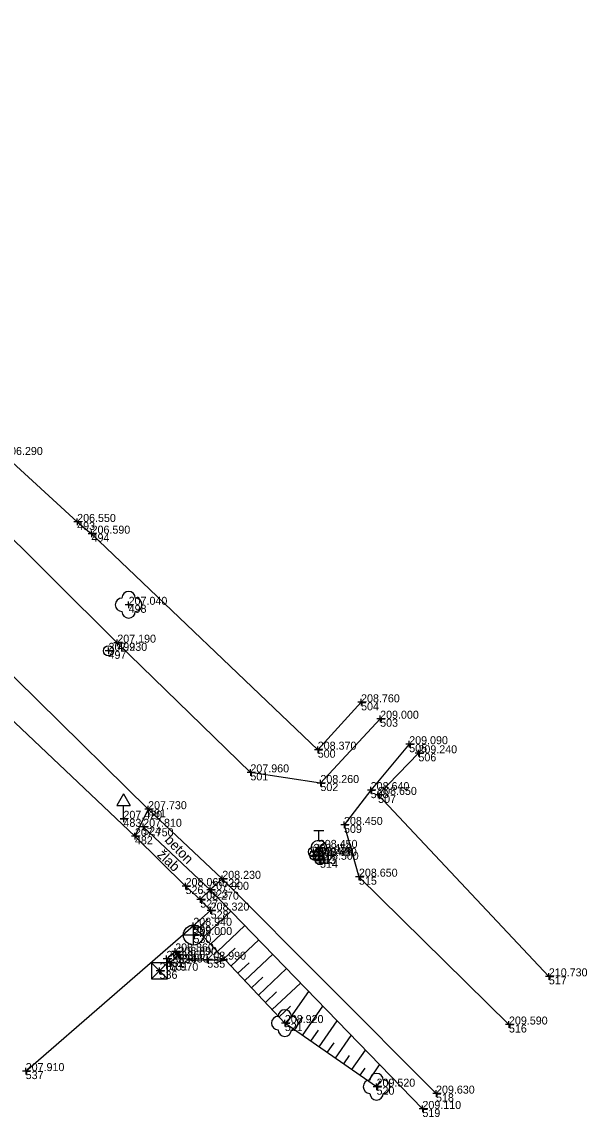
# Model space of a CAD drawing. Extents: x -744883 to -744469, y -966832 to -966374.
# Drawn here: x -744511.3 to -744468.9, y -966832.1 to -966750.1 of the extents above; entities that cross this region are included whole.
import ezdxf

# ---------------------------------------------------------------- set-up
doc = ezdxf.new("R2010")
doc.units = 0
for name, color, linetype in [('Body - výška', 7, 'Continuous'), ('Body - značka', 7, 'Continuous'), ('Body - číslo', 7, 'Continuous'), ('Body polohopisu', 7, 'Continuous'), ('Doplňkové značky', 7, 'Continuous'), ('Nezařazené objekty', 7, 'Continuous'), ('Ploty_opěrné zdi', 7, 'Continuous'), ('Popisy objektů_povrchů', 7, 'Continuous'), ('Rozhraní ploch', 7, 'Continuous'), ('Stromy_porost', 7, 'Continuous'), ('Vrstva 36', 7, 'Continuous'), ('Vstup na pozemek', 7, 'Continuous'), ('Výškopis', 7, 'Continuous'), ('Výšky bodů', 7, 'Continuous'), ('Značky IS', 7, 'Continuous'), ('Čísla bodů', 7, 'Continuous')]:
    doc.layers.add(name, color=color, linetype=linetype)

msp = doc.modelspace()

# ---------------------------------------------------------------- linework, layer by layer
at = {"layer": 'Body - značka'}
for q in [(-744497.66, -966820.35), (-744497.41, -966820.1), (-744497.16, -966820.35), (-744497.41, -966820.6)]:
    msp.add_line((-744497.41, -966820.35), q, dxfattribs=at)
at = {"layer": 'Body polohopisu'}
for p, q in [((-744507.17, -966787.54), (-744507.42, -966787.54)), ((-744507.17, -966787.54), (-744507.17, -966787.29)), ((-744507.17, -966787.54), (-744506.92, -966787.54)), ((-744507.17, -966787.54), (-744507.17, -966787.79)), ((-744506.09, -966788.42), (-744506.34, -966788.42)), ((-744506.09, -966788.42), (-744506.09, -966788.17)), ((-744506.09, -966788.42), (-744505.84, -966788.42)), ((-744506.09, -966788.42), (-744506.09, -966788.67)), ((-744503.31, -966793.75), (-744503.56, -966793.75)), ((-744503.31, -966793.75), (-744503.31, -966793.5)), ((-744503.31, -966793.75), (-744503.06, -966793.75)), ((-744503.31, -966793.75), (-744503.31, -966794)), ((-744504.16, -966796.59), (-744504.41, -966796.59)), ((-744504.16, -966796.59), (-744504.16, -966796.34)), ((-744504.16, -966796.59), (-744503.91, -966796.59)), ((-744504.16, -966796.59), (-744504.16, -966796.84)), ((-744504.82, -966797.2), (-744505.07, -966797.2)), ((-744504.82, -966797.2), (-744504.82, -966796.95)), ((-744504.82, -966797.2), (-744504.57, -966797.2)), ((-744504.82, -966797.2), (-744504.82, -966797.45)), ((-744485.88, -966801.06), (-744485.88, -966800.81)), ((-744485.88, -966801.06), (-744486.13, -966801.06)), ((-744485.88, -966801.06), (-744485.63, -966801.06)), ((-744485.88, -966801.06), (-744485.88, -966801.31)), ((-744484.45, -966802.29), (-744484.7, -966802.29)), ((-744484.45, -966802.29), (-744484.45, -966802.04)), ((-744484.45, -966802.29), (-744484.2, -966802.29)), ((-744484.45, -966802.29), (-744484.45, -966802.54)), ((-744482.27, -966804.2), (-744482.27, -966803.95)), ((-744489.13, -966804.61), (-744489.38, -966804.61)), ((-744489.13, -966804.61), (-744489.13, -966804.36)), ((-744489.13, -966804.61), (-744488.88, -966804.61)), ((-744489.13, -966804.61), (-744489.13, -966804.86)), ((-744482.27, -966804.2), (-744482.52, -966804.2)), ((-744482.27, -966804.2), (-744482.02, -966804.2)), ((-744482.27, -966804.2), (-744482.27, -966804.45)), ((-744481.58, -966804.88), (-744481.83, -966804.88)), ((-744481.58, -966804.88), (-744481.58, -966804.63)), ((-744481.58, -966804.88), (-744481.33, -966804.88)), ((-744481.58, -966804.88), (-744481.58, -966805.13)), ((-744494.18, -966806.31), (-744494.43, -966806.31)), ((-744494.18, -966806.31), (-744494.18, -966806.06)), ((-744494.18, -966806.31), (-744493.93, -966806.31)), ((-744494.18, -966806.31), (-744494.18, -966806.56)), ((-744488.93, -966807.11), (-744489.18, -966807.11)), ((-744488.93, -966807.11), (-744488.93, -966806.86)), ((-744488.93, -966807.11), (-744488.68, -966807.11)), ((-744488.93, -966807.11), (-744488.93, -966807.36)), ((-744485.16, -966807.64), (-744485.16, -966807.39)), ((-744485.16, -966807.64), (-744485.41, -966807.64)), ((-744485.16, -966807.64), (-744484.91, -966807.64)), ((-744485.16, -966807.64), (-744485.16, -966807.89)), ((-744484.6, -966808), (-744484.85, -966808)), ((-744484.6, -966808), (-744484.6, -966807.75)), ((-744484.6, -966808), (-744484.35, -966808)), ((-744484.6, -966808), (-744484.6, -966808.25)), ((-744501.85, -966809.07), (-744501.85, -966808.82)), ((-744503.7, -966809.79), (-744503.95, -966809.79)), ((-744503.7, -966809.79), (-744503.7, -966809.54)), ((-744503.7, -966809.79), (-744503.45, -966809.79)), ((-744503.7, -966809.79), (-744503.7, -966810.04)), ((-744501.85, -966809.07), (-744502.1, -966809.07)), ((-744501.85, -966809.07), (-744501.6, -966809.07)), ((-744501.85, -966809.07), (-744501.85, -966809.32)), ((-744502.22, -966810.39), (-744502.47, -966810.39)), ((-744502.22, -966810.39), (-744502.22, -966810.14)), ((-744502.22, -966810.39), (-744501.97, -966810.39)), ((-744502.22, -966810.39), (-744502.22, -966810.64)), ((-744487.16, -966810.25), (-744487.41, -966810.25)), ((-744487.16, -966810.25), (-744487.16, -966810)), ((-744487.16, -966810.25), (-744486.91, -966810.25)), ((-744487.16, -966810.25), (-744487.16, -966810.5)), ((-744502.84, -966811.1), (-744503.09, -966811.1)), ((-744502.84, -966811.1), (-744502.84, -966810.85)), ((-744502.84, -966811.1), (-744502.59, -966811.1)), ((-744502.84, -966811.1), (-744502.84, -966811.35)), ((-744489.45, -966812.27), (-744489.7, -966812.27)), ((-744489.45, -966812.27), (-744489.45, -966812.02)), ((-744489.45, -966812.27), (-744489.2, -966812.27)), ((-744489.45, -966812.27), (-744489.45, -966812.52)), ((-744489.35, -966812.53), (-744489.35, -966812.28)), ((-744489.05, -966811.97), (-744489.3, -966811.97)), ((-744489.05, -966811.97), (-744489.05, -966811.72)), ((-744489.05, -966811.97), (-744488.8, -966811.97)), ((-744489.05, -966811.97), (-744489.05, -966812.22)), ((-744489.35, -966812.53), (-744489.6, -966812.53)), ((-744489.35, -966812.53), (-744489.1, -966812.53)), ((-744489.35, -966812.53), (-744489.35, -966812.78)), ((-744489.1, -966812.59), (-744489.35, -966812.59)), ((-744488.96, -966812.86), (-744489.21, -966812.86)), ((-744489.1, -966812.59), (-744489.1, -966812.34)), ((-744489.1, -966812.59), (-744488.85, -966812.59)), ((-744489.1, -966812.59), (-744489.1, -966812.84)), ((-744488.96, -966812.86), (-744488.96, -966812.61)), ((-744488.96, -966812.86), (-744488.71, -966812.86)), ((-744488.96, -966812.86), (-744488.96, -966813.11)), ((-744486.04, -966814.13), (-744486.04, -966813.88)), ((-744499.04, -966814.83), (-744499.04, -966814.58)), ((-744496.29, -966814.29), (-744496.54, -966814.29)), ((-744496.29, -966814.29), (-744496.29, -966814.04)), ((-744496.29, -966814.29), (-744496.04, -966814.29)), ((-744496.29, -966814.29), (-744496.29, -966814.54)), ((-744486.04, -966814.13), (-744486.29, -966814.13)), ((-744486.04, -966814.13), (-744485.79, -966814.13)), ((-744486.04, -966814.13), (-744486.04, -966814.38)), ((-744499.04, -966814.83), (-744499.29, -966814.83)), ((-744499.04, -966814.83), (-744498.79, -966814.83)), ((-744499.04, -966814.83), (-744499.04, -966815.08)), ((-744497.94, -966815.85), (-744497.94, -966815.6)), ((-744497.19, -966815.11), (-744497.44, -966815.11)), ((-744497.19, -966815.11), (-744497.19, -966814.86)), ((-744497.19, -966815.11), (-744496.94, -966815.11)), ((-744497.19, -966815.11), (-744497.19, -966815.36)), ((-744497.94, -966815.85), (-744498.19, -966815.85)), ((-744497.94, -966815.85), (-744497.69, -966815.85)), ((-744497.94, -966815.85), (-744497.94, -966816.1)), ((-744497.16, -966816.67), (-744497.16, -966816.42)), ((-744497.16, -966816.67), (-744497.41, -966816.67)), ((-744497.16, -966816.67), (-744496.91, -966816.67)), ((-744497.16, -966816.67), (-744497.16, -966816.92)), ((-744498.46, -966817.81), (-744498.71, -966817.81)), ((-744498.46, -966817.81), (-744498.46, -966817.56)), ((-744498.46, -966817.81), (-744498.21, -966817.81)), ((-744498.46, -966817.81), (-744498.46, -966818.06)), ((-744498.45, -966818.5), (-744498.7, -966818.5)), ((-744498.45, -966818.5), (-744498.45, -966818.25)), ((-744498.45, -966818.5), (-744498.2, -966818.5)), ((-744498.45, -966818.5), (-744498.45, -966818.75)), ((-744499.82, -966819.73), (-744499.82, -966819.48)), ((-744500.47, -966820.29), (-744500.72, -966820.29)), ((-744500.47, -966820.29), (-744500.47, -966820.04)), ((-744500.47, -966820.29), (-744500.22, -966820.29)), ((-744500.47, -966820.29), (-744500.47, -966820.54)), ((-744500.21, -966820.56), (-744500.21, -966820.31)), ((-744499.82, -966819.73), (-744500.07, -966819.73)), ((-744499.58, -966819.99), (-744499.83, -966819.99)), ((-744499.82, -966819.73), (-744499.57, -966819.73)), ((-744499.82, -966819.73), (-744499.82, -966819.98)), ((-744499.58, -966819.99), (-744499.58, -966819.74)), ((-744499.58, -966819.99), (-744499.33, -966819.99)), ((-744499.58, -966819.99), (-744499.58, -966820.24)), ((-744500.99, -966821.18), (-744501.24, -966821.18)), ((-744500.99, -966821.18), (-744500.99, -966820.93)), ((-744500.99, -966821.18), (-744500.74, -966821.18)), ((-744500.99, -966821.18), (-744500.99, -966821.43)), ((-744500.21, -966820.56), (-744500.46, -966820.56)), ((-744500.21, -966820.56), (-744499.96, -966820.56)), ((-744500.21, -966820.56), (-744500.21, -966820.81)), ((-744471.8, -966821.6), (-744471.8, -966821.35)), ((-744471.8, -966821.6), (-744472.05, -966821.6)), ((-744471.8, -966821.6), (-744471.55, -966821.6)), ((-744471.8, -966821.6), (-744471.8, -966821.85)), ((-744491.6, -966825.1), (-744491.85, -966825.1)), ((-744491.6, -966825.1), (-744491.6, -966824.85)), ((-744491.6, -966825.1), (-744491.35, -966825.1)), ((-744491.6, -966825.1), (-744491.6, -966825.35)), ((-744474.79, -966825.21), (-744475.04, -966825.21)), ((-744474.79, -966825.21), (-744474.79, -966824.96)), ((-744474.79, -966825.21), (-744474.54, -966825.21)), ((-744474.79, -966825.21), (-744474.79, -966825.46)), ((-744511.03, -966828.7), (-744511.28, -966828.7)), ((-744511.03, -966828.7), (-744511.03, -966828.45)), ((-744511.03, -966828.7), (-744510.78, -966828.7)), ((-744511.03, -966828.7), (-744511.03, -966828.95)), ((-744484.72, -966829.87), (-744484.97, -966829.87)), ((-744484.72, -966829.87), (-744484.72, -966829.62)), ((-744484.72, -966829.87), (-744484.47, -966829.87)), ((-744484.72, -966829.87), (-744484.72, -966830.12)), ((-744480.26, -966830.39), (-744480.26, -966830.14)), ((-744480.26, -966830.39), (-744480.51, -966830.39)), ((-744480.26, -966830.39), (-744480.01, -966830.39)), ((-744480.26, -966830.39), (-744480.26, -966830.64)), ((-744481.28, -966831.54), (-744481.53, -966831.54)), ((-744481.28, -966831.54), (-744481.28, -966831.29)), ((-744481.28, -966831.54), (-744481.03, -966831.54)), ((-744481.28, -966831.54), (-744481.28, -966831.79))]:
    msp.add_line(p, q, dxfattribs=at)
at = {"layer": 'Doplňkové značky'}
for p, q in [((-744503.7, -966807.924), (-744504.2, -966808.79)), ((-744503.7, -966807.924), (-744503.2, -966808.79)), ((-744504.2, -966808.79), (-744503.2, -966808.79)), ((-744503.7, -966809.79), (-744503.7, -966808.79)), ((-744503.95, -966809.79), (-744503.45, -966809.79))]:
    msp.add_line(p, q, dxfattribs=at)
at = {"layer": 'Nezařazené objekty'}
msp.add_lwpolyline([(-744497.19, -966815.11), (-744502.22, -966810.39)], dxfattribs=at)
at = {"layer": 'Ploty_opěrné zdi'}
for points in [[(-744512.65, -966782.52), (-744507.17, -966787.54)], [(-744506.09, -966788.42), (-744489.13, -966804.61), (-744485.88, -966801.06)], [(-744502.84, -966811.1), (-744520.37, -966794.52)], [(-744481.58, -966804.88), (-744484.6, -966808), (-744471.8, -966821.6)], [(-744511.03, -966828.7), (-744498.46, -966817.81), (-744497.16, -966816.67), (-744497.94, -966815.85), (-744499.04, -966814.83)]]:
    msp.add_lwpolyline(points, dxfattribs=at)
at = {"layer": 'Rozhraní ploch'}
for points in [[(-744484.45, -966802.29), (-744488.93, -966807.11), (-744494.18, -966806.31), (-744504.16, -966796.59), (-744523.84, -966777.07), (-744535.89, -966765.33), (-744540.85, -966760.58), (-744553.38, -966748.22), (-744567.31, -966735.07), (-744575.15, -966727.6), (-744592.64, -966710.64), (-744593.17, -966705.66)], [(-744534.31, -966781.3), (-744531.64, -966779.92), (-744518.41, -966792.79), (-744501.85, -966809.07), (-744502.84, -966811.1)], [(-744482.27, -966804.2), (-744485.16, -966807.64), (-744487.16, -966810.25), (-744486.04, -966814.13), (-744474.79, -966825.21)], [(-744501.85, -966809.07), (-744496.29, -966814.29)], [(-744480.26, -966830.39), (-744496.29, -966814.29), (-744497.19, -966815.11), (-744497.94, -966815.85)]]:
    msp.add_lwpolyline(points, dxfattribs=at)
at = {"layer": 'Stromy_porost'}
for centre in [(-744503.31, -966793.75), (-744491.6, -966825.1), (-744484.72, -966829.87)]:
    msp.add_circle(centre, 0.0005, dxfattribs=at)
for centre, start, end in [((-744503.81, -966793.75), 89.99999, 269.99999), ((-744503.31, -966793.25), 0, 179.99999), ((-744502.81, -966793.75), 270, 89.99999), ((-744503.31, -966794.25), 179.99999, 359.99999), ((-744492.1, -966825.1), 89.99999, 269.99999), ((-744491.6, -966824.6), 0, 179.99999), ((-744491.1, -966825.1), 270, 89.99999), ((-744491.6, -966825.6), 179.99999, 359.99999), ((-744485.22, -966829.87), 89.99999, 269.99999), ((-744484.72, -966829.37), 0, 179.99999), ((-744484.22, -966829.87), 270, 89.99999), ((-744484.72, -966830.37), 179.99999, 359.99999)]:
    msp.add_arc(centre, 0.5, start, end, dxfattribs=at)
at = {"layer": 'Vrstva 36'}
msp.add_line((-744498.91, -966820.35), (-744495.91, -966820.35), dxfattribs=at)
msp.add_lwpolyline([(-744496.91, -966820.1), (-744495.91, -966820.35), (-744496.91, -966820.6)], dxfattribs=at)
at = {"layer": 'Vstup na pozemek'}
for points in [[(-744507.17, -966787.54), (-744506.09, -966788.42)], [(-744499.04, -966814.83), (-744502.84, -966811.1)]]:
    msp.add_lwpolyline(points, dxfattribs=at)
at = {"layer": 'Výškopis'}
for points in [[(-744481.28, -966831.54), (-744497.19, -966815.11)], [(-744497.684, -966818.634), (-744495.64, -966816.711)], [(-744484.72, -966829.87), (-744491.6, -966825.1), (-744498.46, -966817.81)], [(-744498.198, -966818.088), (-744497.384, -966817.322)], [(-744496.656, -966819.727), (-744494.596, -966817.788)], [(-744497.17, -966819.181), (-744496.349, -966818.408)], [(-744495.628, -966820.819), (-744493.553, -966818.866)], [(-744496.142, -966820.273), (-744495.315, -966819.495)], [(-744494.6, -966821.912), (-744492.509, -966819.944)], [(-744495.114, -966821.365), (-744494.281, -966820.581)], [(-744493.572, -966823.004), (-744491.466, -966821.021)], [(-744494.086, -966822.458), (-744493.247, -966821.668)], [(-744492.544, -966824.096), (-744490.422, -966822.099)], [(-744493.058, -966823.55), (-744492.213, -966822.754)], [(-744491.5, -966825.169), (-744489.81, -966822.732)], [(-744492.03, -966824.643), (-744491.178, -966823.841)], [(-744490.267, -966826.024), (-744488.746, -966823.83)], [(-744490.884, -966825.597), (-744490.241, -966824.67)], [(-744489.034, -966826.879), (-744487.682, -966824.928)], [(-744489.651, -966826.451), (-744489.076, -966825.623)], [(-744487.802, -966827.733), (-744486.619, -966826.027)], [(-744488.418, -966827.306), (-744487.911, -966826.575)], [(-744487.185, -966828.161), (-744486.746, -966827.527)], [(-744486.569, -966828.588), (-744485.555, -966827.125)], [(-744485.953, -966829.015), (-744485.581, -966828.479)], [(-744485.336, -966829.443), (-744484.491, -966828.224)], [(-744484.72, -966829.87), (-744484.416, -966829.431)]]:
    msp.add_lwpolyline(points, dxfattribs=at)
at = {"layer": 'Značky IS'}
for p, q in [((-744489.425, -966810.657), (-744488.675, -966810.657)), ((-744489.05, -966811.407), (-744489.05, -966810.657)), ((-744489.491, -966812.317), (-744488.606, -966811.622)), ((-744498.451, -966819.248), (-744498.45, -966817.753)), ((-744497.698, -966818.506), (-744499.198, -966818.501)), ((-744501.59, -966820.58), (-744500.39, -966821.78)), ((-744500.39, -966820.58), (-744501.59, -966821.78))]:
    msp.add_line(p, q, dxfattribs=at)
msp.add_lwpolyline([(-744499.58, -966819.99), (-744500.21, -966820.56), (-744500.47, -966820.29), (-744499.82, -966819.73), (-744499.58, -966819.99)], dxfattribs=at)
msp.add_lwpolyline([(-744501.59, -966821.78), (-744500.39, -966821.78), (-744500.39, -966820.58), (-744501.59, -966820.58)], close=True, dxfattribs=at)
for centre, radius in [((-744504.82, -966797.2), 0.375), ((-744489.05, -966811.97), 0.562), ((-744489.45, -966812.27), 0.375), ((-744489.35, -966812.53), 0.375), ((-744489.1, -966812.59), 0.375), ((-744488.96, -966812.86), 0.375), ((-744498.45, -966818.5), 0.75)]:
    msp.add_circle(centre, radius, dxfattribs=at)

# ---------------------------------------------------------------- texts
at = {"layer": 'Body - výška'}
msp.add_text('208.990', height=0.6, dxfattribs=at).set_placement((-744497.41, -966820.35))
at = {"layer": 'Body - číslo'}
msp.add_text('535', height=0.6, dxfattribs=at).set_placement((-744497.41, -966820.95))
at = {"layer": 'Popisy objektů_povrchů'}
for s, rotation, p in [('beton', 314.01601, (-744500.66, -966811.431)), ('žlab', 316.8211, (-744501.231, -966812.552))]:
    msp.add_text(s, height=0.75, rotation=rotation, dxfattribs=at).set_placement(p)
at = {"layer": 'Výšky bodů'}
for s, p in [('206.290', (-744512.65, -966782.52)), ('206.550', (-744507.17, -966787.54)), ('206.590', (-744506.09, -966788.42)), ('207.040', (-744503.31, -966793.75)), ('207.230', (-744504.82, -966797.2)), ('207.190', (-744504.16, -966796.59)), ('208.760', (-744485.88, -966801.06)), ('209.000', (-744484.45, -966802.29)), ('208.370', (-744489.13, -966804.61)), ('209.090', (-744482.27, -966804.2)), ('209.240', (-744481.58, -966804.88)), ('207.960', (-744494.18, -966806.31)), ('208.260', (-744488.93, -966807.11)), ('208.640', (-744485.16, -966807.64)), ('208.650', (-744484.6, -966808)), ('207.730', (-744501.85, -966809.07)), ('207.420', (-744503.7, -966809.79)), ('207.810', (-744502.22, -966810.39)), ('208.450', (-744487.16, -966810.25)), ('207.750', (-744502.84, -966811.1)), ('208.450', (-744489.05, -966811.97)), ('208.450', (-744489.45, -966812.27)), ('208.470', (-744489.35, -966812.53)), ('208.480', (-744489.1, -966812.59)), ('208.500', (-744488.96, -966812.86)), ('208.230', (-744496.29, -966814.29)), ('208.650', (-744486.04, -966814.13)), ('208.060', (-744499.04, -966814.83)), ('207.900', (-744497.19, -966815.11)), ('208.270', (-744497.94, -966815.85)), ('208.320', (-744497.16, -966816.67)), ('208.940', (-744498.46, -966817.81)), ('209.000', (-744498.45, -966818.5)), ('208.860', (-744500.47, -966820.29)), ('208.860', (-744499.82, -966819.73)), ('208.890', (-744499.58, -966819.99)), ('208.880', (-744500.21, -966820.56)), ('208.970', (-744500.99, -966821.18)), ('210.730', (-744471.8, -966821.6)), ('208.920', (-744491.6, -966825.1)), ('209.590', (-744474.79, -966825.21)), ('207.910', (-744511.03, -966828.7)), ('209.520', (-744484.72, -966829.87)), ('209.630', (-744480.26, -966830.39)), ('209.110', (-744481.28, -966831.54))]:
    msp.add_text(s, height=0.6, dxfattribs=at).set_placement(p)
at = {"layer": 'Čísla bodů'}
for s, p in [('493', (-744507.17, -966788.14)), ('494', (-744506.09, -966789.02)), ('498', (-744503.31, -966794.35)), ('499', (-744504.16, -966797.19)), ('497', (-744504.82, -966797.8)), ('504', (-744485.88, -966801.66)), ('503', (-744484.45, -966802.89)), ('500', (-744489.13, -966805.21)), ('505', (-744482.27, -966804.8)), ('506', (-744481.58, -966805.48)), ('501', (-744494.18, -966806.91)), ('502', (-744488.93, -966807.71)), ('508', (-744485.16, -966808.24)), ('507', (-744484.6, -966808.6)), ('483', (-744503.7, -966810.39)), ('481', (-744501.85, -966809.67)), ('524', (-744502.22, -966810.99)), ('509', (-744487.16, -966810.85)), ('482', (-744502.84, -966811.7)), ('511', (-744489.45, -966812.87)), ('510', (-744489.05, -966812.57)), ('512', (-744489.35, -966813.13)), ('513', (-744489.1, -966813.19)), ('514', (-744488.96, -966813.46)), ('522', (-744496.29, -966814.89)), ('515', (-744486.04, -966814.73)), ('526', (-744499.04, -966815.43)), ('523', (-744497.19, -966815.71)), ('527', (-744497.94, -966816.45)), ('528', (-744497.16, -966817.27)), ('529', (-744498.46, -966818.41)), ('530', (-744498.45, -966819.1)), ('532', (-744500.47, -966820.89)), ('533', (-744499.82, -966820.33)), ('534', (-744499.58, -966820.59)), ('536', (-744500.99, -966821.78)), ('531', (-744500.21, -966821.16)), ('517', (-744471.8, -966822.2)), ('521', (-744491.6, -966825.7)), ('516', (-744474.79, -966825.81)), ('537', (-744511.03, -966829.3)), ('520', (-744484.72, -966830.47)), ('518', (-744480.26, -966830.99)), ('519', (-744481.28, -966832.14))]:
    msp.add_text(s, height=0.6, dxfattribs=at).set_placement(p)

doc.saveas('drawing.dxf')
